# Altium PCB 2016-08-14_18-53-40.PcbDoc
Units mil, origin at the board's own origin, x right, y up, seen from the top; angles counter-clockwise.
Board outline 2000 x 2000 mil, 4 copper layers (Top Layer, MidLayer1, MidLayer2, Bottom Layer); 21 components, 10 nets, 46 pads, 49 vias.
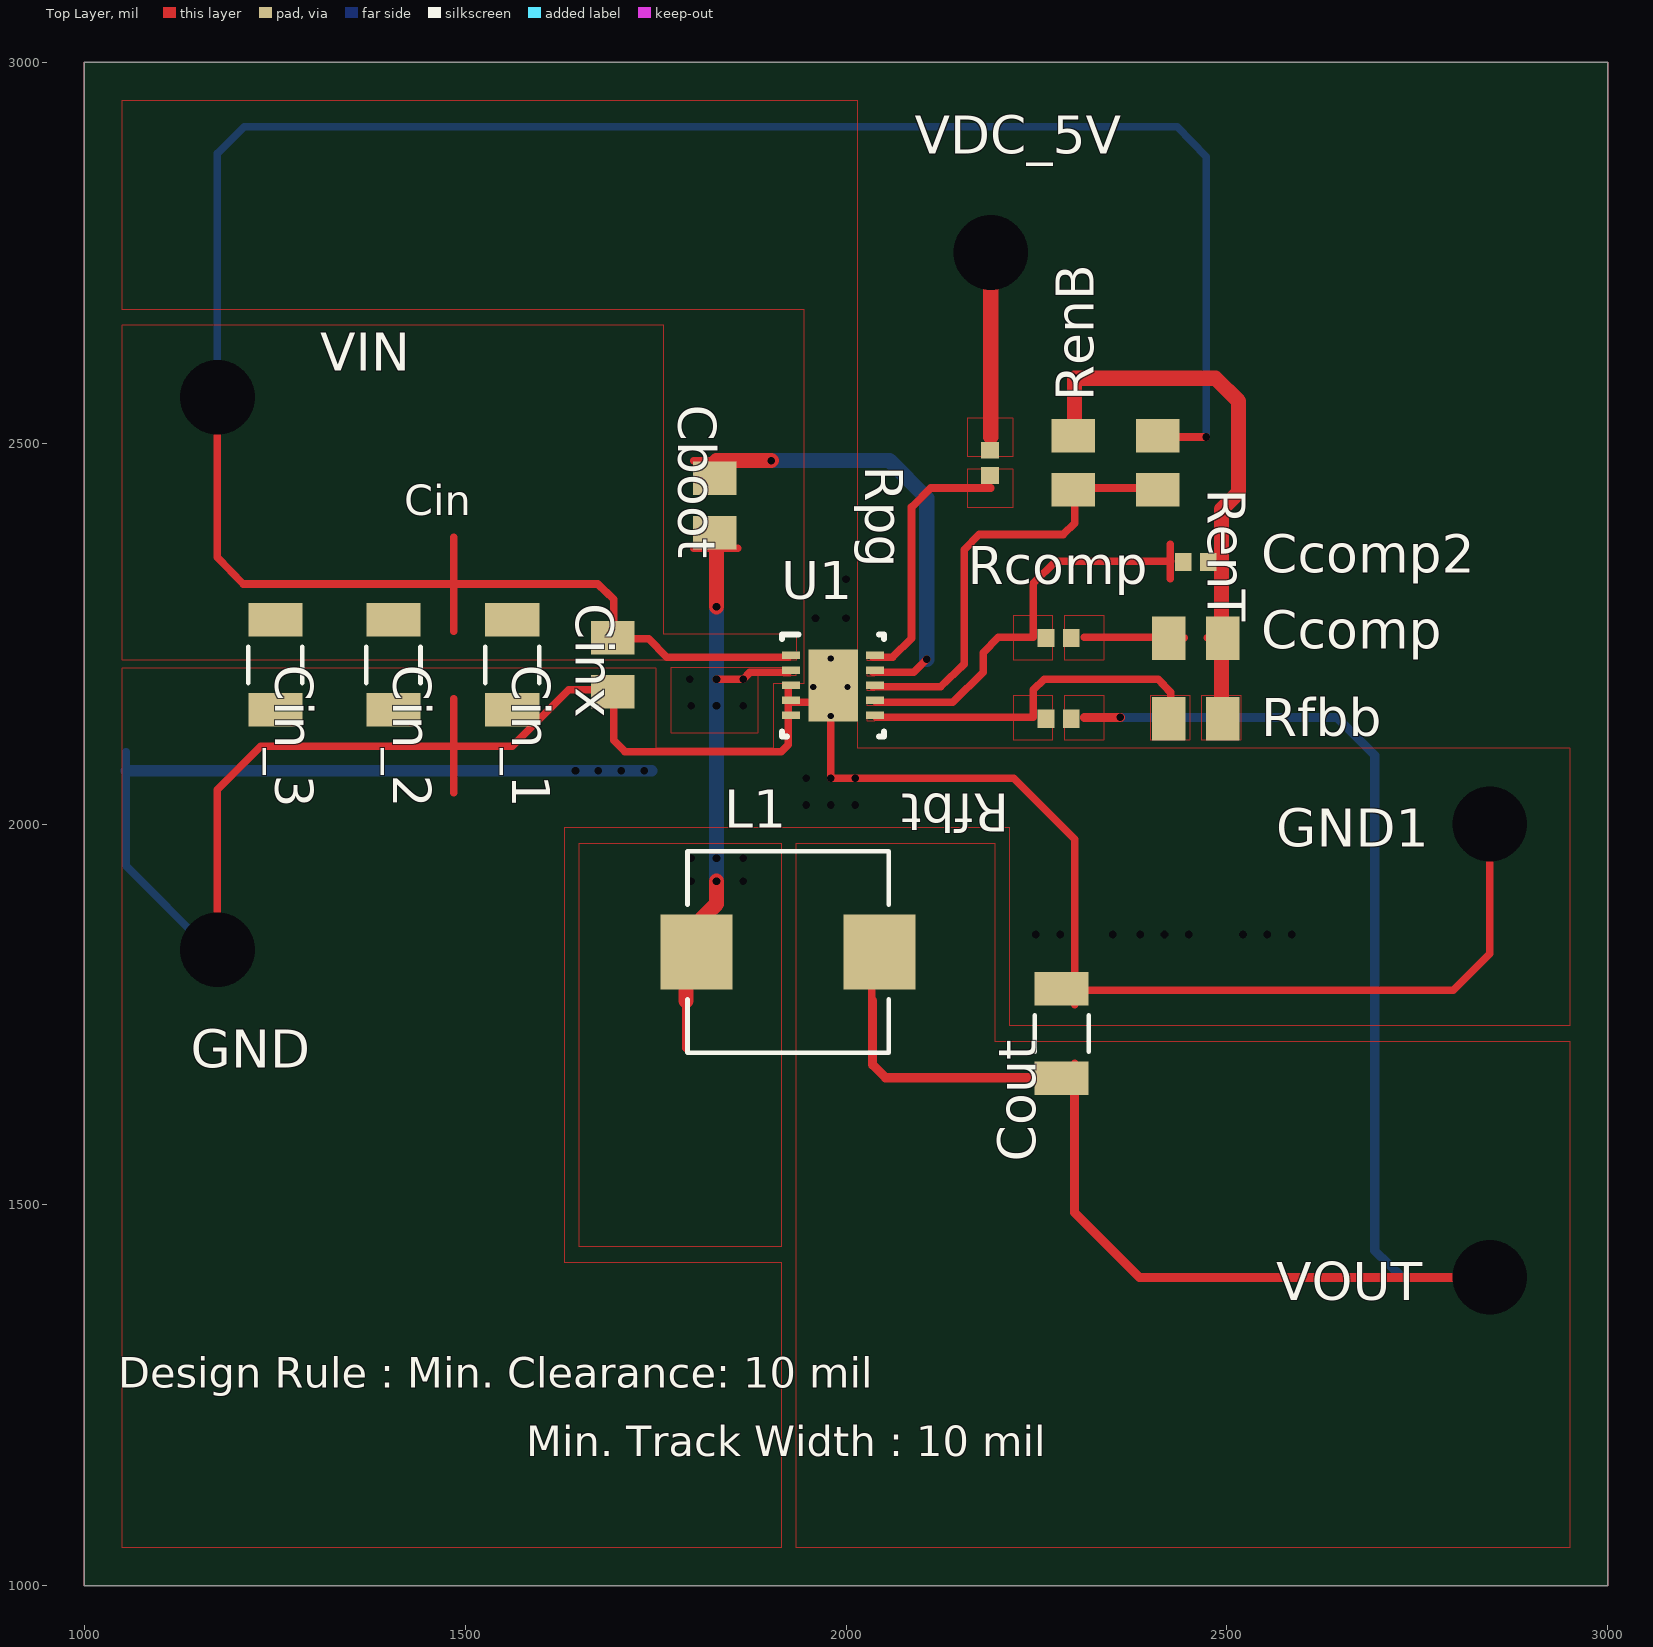
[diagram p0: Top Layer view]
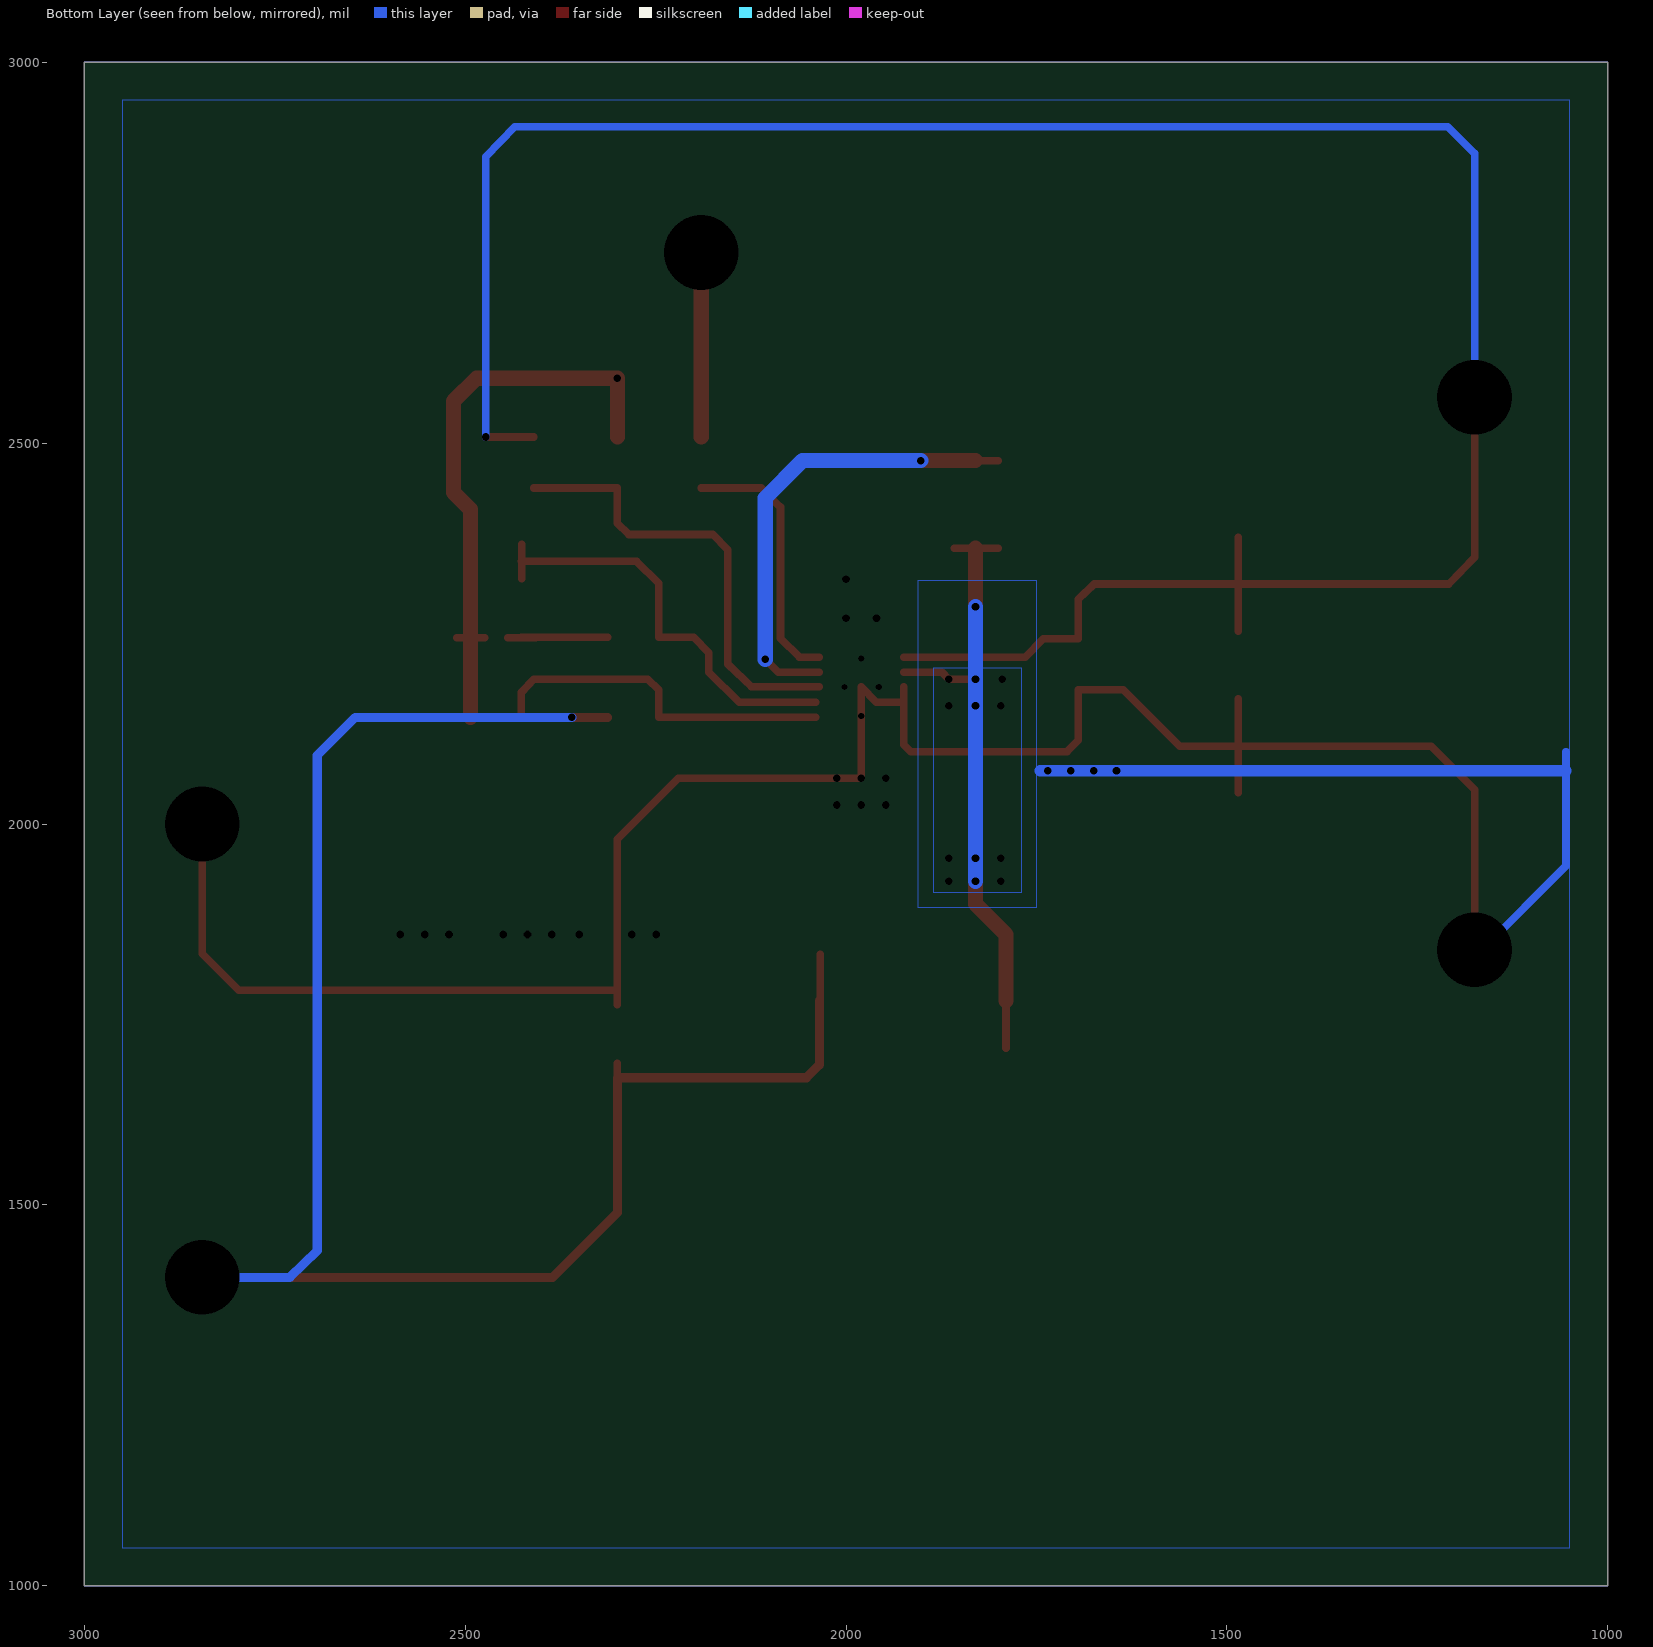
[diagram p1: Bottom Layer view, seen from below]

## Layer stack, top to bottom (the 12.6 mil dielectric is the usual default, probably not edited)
Top Layer: signal copper 1.4
Dielectric: core 12.6, FR-4, Dk 4.8
MidLayer1: signal copper 1.4
Dielectric: prepreg 12.6, FR-4, Dk 4.8
MidLayer2: signal copper 1.4
Dielectric: core 12.6, FR-4, Dk 4.8
Bottom Layer: signal copper 1.4

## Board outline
1000,1000 3000,1000 3000,3000 1000,3000

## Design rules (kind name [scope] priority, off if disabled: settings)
PlaneConnect [All] p0: scope1count=1 scope1_0_kind=Board scope1_0_value=Board scope2count=1 scope2_0_kind=Board scope2_0_value=Board commentlength=0 planeconnectstyle=Direct reliefexpansion=20 reliefentries=4 reliefconductorwidth=10 reliefairgap=10
PlaneConnect [All] p1: planeconnectstyle=Direct reliefexpansion=20 reliefentries=4 reliefconductorwidth=10 reliefairgap=10
PolygonConnect [All] p0: scope1count=1 scope1_0_kind=Board scope1_0_value=Board scope2count=1 scope2_0_kind=Board scope2_0_value=Board commentlength=0 connectstyle=Direct reliefconductorwidth=10 reliefentries=4 polygonreliefangle="90 Angle"
PolygonConnect [All] p1: connectstyle=Direct reliefconductorwidth=10 reliefentries=4 polygonreliefangle="90 Angle"

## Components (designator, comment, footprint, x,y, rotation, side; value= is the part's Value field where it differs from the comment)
Cboot "" 0805 1828,2418 r270 top
Ccomp "" 0805 2459,2244 r0 top
Ccomp2 "" 0402 2459,2344 r0 top
Cin_1 "" 1206 1562,2209 r270 top
Cin_2 "" 1206 1406,2209 r270 top
Cin_3 "" 1206 1251,2209 r270 top
Cinx "" 0805 1694,2209 r270 top
Cout "" 1206_190 2283,1725 r90 top
GND "" TP-1502 1173,1834 r0 top
GND1 "" TP-1502 2844,2000 r0 top
L1 "" SRP7030 1924,1832 r0 top
Rcomp "" 0402 2279,2244 r0 top
RenB "" 0805 2298,2474 r90 top
RenT "" 0805 2409,2474 r270 top
Rfbb "" 0805 2459,2138 r0 top
Rfbt "" 0402 2279,2138 r180 top
Rpg "" 0402 2189,2474 r270 top
U1 "" DRC0010J 1983,2182 r0 top
VDC_5V "" TP-1502 2189,2749 r0 top
VIN "" TP-1502 1173,2559 r0 top
VOUT "" TP-1502 2844,1405 r0 top

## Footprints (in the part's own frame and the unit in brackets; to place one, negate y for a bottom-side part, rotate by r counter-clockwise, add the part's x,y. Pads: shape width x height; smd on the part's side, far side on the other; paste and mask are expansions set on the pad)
0402 [mil]
  rect 22x24 smd: 1(-16.5,0) 2(16.5,0)
0805 [mil]
  rect 44x57 smd: 1(-35.5,0) 2(35.5,0)
1206 [mil]
  rect 44x71 smd: 1(-59,0) 2(59,0)
  silkscreen extent -24,-36 24,36
1206_190 [mil]
  rect 44x71 smd: 1(-59,0) 2(59,0)
  silkscreen extent -24,-36 24,36
DRC0010J [mm]
  rect 0.6x0.24 smd: 1(-1.4,1) 2(-1.4,0.5) 3(-1.4,0) 4(-1.4,-0.5) 5(-1.4,-1) 6(1.4,-1) 7(1.4,-0.5) 8(1.4,0) 9(1.4,0.5) 10(1.4,1)
  rect 1.65x2.4 smd: 11(0,0)
  silkscreen extent -1.7,-1.7 1.7,1.7
SRP7030 [mil]
  rect 94.5x98 smd: 1(-120.25,0) 2(120.25,0)
  silkscreen extent -132,-132 132,132
TP-1502 [mil]
  round 65 / inner round 0 / far side round 65 hole 32: 1(0,0)

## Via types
v1: diameter 0, hole 10, Top Layer to Bottom Layer, 40 vias
v2: diameter 0, hole 98, Top Layer to Bottom Layer, 5 vias
v3: diameter 0, hole 8, Top Layer to Bottom Layer, 4 vias

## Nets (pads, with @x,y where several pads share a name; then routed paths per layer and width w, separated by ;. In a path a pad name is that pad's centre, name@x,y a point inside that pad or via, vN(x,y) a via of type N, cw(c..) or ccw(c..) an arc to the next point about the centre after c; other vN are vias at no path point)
0: Ccomp2.2 Ccomp.2 Cin_1.2 Cin_2.2 Cin_3.2 Cinx.2 Cout.2 GND1.1 GND.1 RenB.2 Rfbb.2 U1.3 U1.4 U1.5 U1.11 | length 4611.6
  Top Layer w10: v2(1175,1835) 1175,2045 1232,2102 1485,2102 1562,2102 1636,2176 1695,2176 1695,2110 1710,2095 1915,2095 1924,2104 1924,2140 U1.4@1924,2160 ; 1485,2041 1485,2164 ; U1.3@1924,2180 U1.4@1924,2160 ; Cout.2@2300,1763 Cout.2@2300,1800 ; Ccomp.2@2474,2244.5 Ccomp.2@2511,2244.5 ; 2492.5,2322 2492.5,2367 ; v2(2845,2000) 2845,1830 2797,1782 2300,1782 2300,1980 2220,2060 v1(2012,2060) v1(1980,2060) 1980,2180 1960,2160 U1.4@1924,2160
  Top Layer w20: RenB.2@2300,2508 v1(2300,2585) 2485,2585 2515,2555 2515,2435 2493,2413 2493,2345 2493,2245 Rfbb.2@2493,2140
  Bottom Layer w10: 1055,2095 1055,2070 1055,1945 1165,1835 v2(1175,1835)
  Bottom Layer w15: 1055,2070 v1(1645,2070) v1(1675,2070) v1(1705,2070) v1(1735,2070) 1745,2070
  other v1: 2249,1855 2281,1855 2350,1855 2386,1855 2418,1855 2450,1855 2521,1855 2553,1855 2585,1855 1948,2025 1980,2025 2012,2025 1948,2060 1960,2270 2000,2270 2000,2321
  other v3: 1980,2142 1957,2180 2002,2180 1980,2217
1: Ccomp.1 Rcomp.2 | length 150
  Top Layer w10: 2313,2245 Ccomp.1@2426,2245 ; Ccomp.1@2407,2244.5 Ccomp.1@2444,2244.5
2: Cboot.1 Ccomp2.1 Rcomp.1 U1.7 U1.9 | length 1208.5
  Top Layer w10: 1800,2477 1858,2477 ; U1.9@2035,2199 2089,2199 v1(2106,2216) ; U1.7@2040,2160 2140,2160 2180,2199 2180,2225 2200,2245 2246,2245 2246,2316 2275,2345 2426,2345 ; 2425.5,2322 2425.5,2367
  Top Layer w20: 1830,2477 v1(1902,2477)
  Bottom Layer w20: v1(1902,2477) 2057,2477 2106,2428 v1(2106,2216)
3: Rfbb.1 Rfbt.2 U1.6 | length 468.1
  Top Layer w10: U1.6@2040,2140 2245,2140 2246,2140 2246,2176 2260,2190 2410,2190 2426,2173 Rfbb.1@2426,2140
4: Cboot.2 L1.1 U1.2 | length 889.3
  Top Layer w10: 1790,1706 L1.1@1790,1829 ; Cboot.2@1800,2362 1858,2362 ; v1(1830,2190) v1(1865,2190) 1874,2199 U1.2@1924,2199
  Top Layer w20: 1790,1768 1790,1855 1830,1895 v1(1830,1925) ; v1(1830,2285) Cboot.2@1830,2362
  Bottom Layer w10: 1830,2189 v1(1830,2190)
  Bottom Layer w20: v1(1830,1925) v1(1830,1955) v1(1830,2155) 1830,2189 ; v1(1830,2190) v1(1830,2285)
  other v1: 1797,1925 1865,1925 1797,1955 1865,1955 1797,2155 1865,2155 1795,2190
5: Cout.1 L1.2 Rfbt.1 VOUT.1 | length 2515.2
  Top Layer w10: 2034,1706 L1.2@2034,1829 ; Cout.1@2300,1649 Cout.1@2300,1686
  Top Layer w12: 2035,1768 2035,1684 2052,1667 2300,1667 2300,1490 2385,1405 v2(2845,1405) VOUT.1@2870,1405 ; 2313,2140 v1(2360,2140)
  Bottom Layer w12: v1(2360,2140) 2644,2140 2694,2090 2694,1440 2730,1405 v2(2845,1405)
6: Cin_1.1 Cin_2.1 Cin_3.1 Cinx.1 RenT.1 U1.1 VIN.1 | length 3246.7
  Top Layer w10: v2(1175,2560) 1175,2350 1209,2315 1485,2315 1674,2315 1695,2295 1695,2243 1741,2243 1765,2219 U1.1@1924,2219 ; 1485,2253 1485,2376 ; RenT.1@2410,2508 v1(2473,2508)
  Bottom Layer w10: v2(1175,2560) 1175,2880 1210,2915 2435,2915 2473,2876 v1(2473,2508)
8: RenB.1 RenT.2 U1.8 | length 597.6
  Top Layer w10: U1.8@2035,2180 2124,2180 2155,2210 2155,2360 2175,2380 2285,2380 2300,2395 2300,2441 RenT.2@2410,2441
13: Rpg.2 U1.10 | length 347.7
  Top Layer w10: U1.10@2035,2219 2061,2219 2086,2244 2086,2416 2111,2441 2190,2441
17: Rpg.1 VDC_5V.1 | length 242
  Top Layer w20: 2190,2508 v2(2190,2750)

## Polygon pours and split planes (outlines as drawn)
2 on Top Layer " " (solid, pour order 0): 2220,2215 2220,2274 2271,2274 2271,2215
1 on Top Layer " " (solid, pour order 1): 2287,2215 2287,2274 2338,2274 2338,2215
13 on Top Layer " " (solid, pour order 2): 2160,2415 2160,2466 2219,2466 2219,2415
17 on Top Layer " " (solid, pour order 3): 2160,2482 2160,2533 2219,2533 2219,2482
3 on Top Layer " " (solid, pour order 4): 2400,2110 2400,2169 2451,2169 2451,2110
3 on Top Layer " " (solid, pour order 5): 2220,2110 2220,2169 2271,2169 2271,2110
5 on Top Layer " " (solid, pour order 6): 2287,2110 2287,2169 2338,2169 2338,2110
6 on Top Layer " " (solid, pour order 7): 1918,2214 1918,2223 1927,2223 1927,2214
4 on Top Layer " " (solid, pour order 8): 1918,2194 1918,2203 1927,2203 1927,2194
3 on Top Layer " " (solid, pour order 9): 2028,2135 2028,2144 2037,2144 2037,2135
2 on Top Layer " " (solid, pour order 10): 2028,2155 2028,2164 2037,2164 2037,2155
8 on Top Layer " " (solid, pour order 11): 2028,2175 2028,2184 2037,2184 2037,2175
2 on Top Layer " " (solid, pour order 12): 2028,2194 2028,2203 2037,2203 2037,2194
13 on Top Layer " " (solid, pour order 13): 2028,2214 2028,2223 2037,2223 2037,2214
4 on Top Layer " " (solid, pour order 15): 1650,1975 1915,1975 1915,1445 1650,1445
5 on Top Layer " " (solid, pour order 16): 1935,1975 2195,1975 2195,1715 2950,1715 2950,1050 1935,1050
4 on Top Layer " " (solid, pour order 17): 1935,2205 1770,2205 1770,2120 1885,2120 1885,2195 1935,2195
6 on Top Layer " " (solid, pour order 18): 1935,2215 1050,2215 1050,2655 1760,2655 1760,2570 1760,2285 1760,2250 1935,2250
0 on Top Layer " " (solid, pour order 19): 2467,2110 2467,2169 2518,2169 2518,2110
0 on Top Layer " " (solid, pour order 21): 2015,2220 2015,2100 2950,2100 2950,1735 2215,1735 2215,1995 1630,1995 1630,1425 1915,1425 1915,1050 1050,1050 1050,2205 1750,2205 1750,2100 1905,2100 1905,2185 1945,2185 1945,2315 1945,2675 1050,2675 1050,2950 2015,2950
4 on Bottom Layer " " (solid, pour order 14): 1770,2205 1770,1910 1885,1910 1885,2205
0 on Bottom Layer " " (solid, pour order 20): 1905,2320 1750,2320 1750,2075 1050,2075 1050,2950 2950,2950 2950,1050 1050,1050 1050,2065 1750,2065 1750,1890 1905,1890

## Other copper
Multi-Layer:
  the board outline again, w1

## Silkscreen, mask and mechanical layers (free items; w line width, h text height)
Top Overlay:
  text "Cin" at 1420,2405 h40
  text "Design Rule : Min. Clearance: 10 mil" at 1045,1260 h40
  text "Min. Track Width : 10 mil" at 1580,1170 h40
